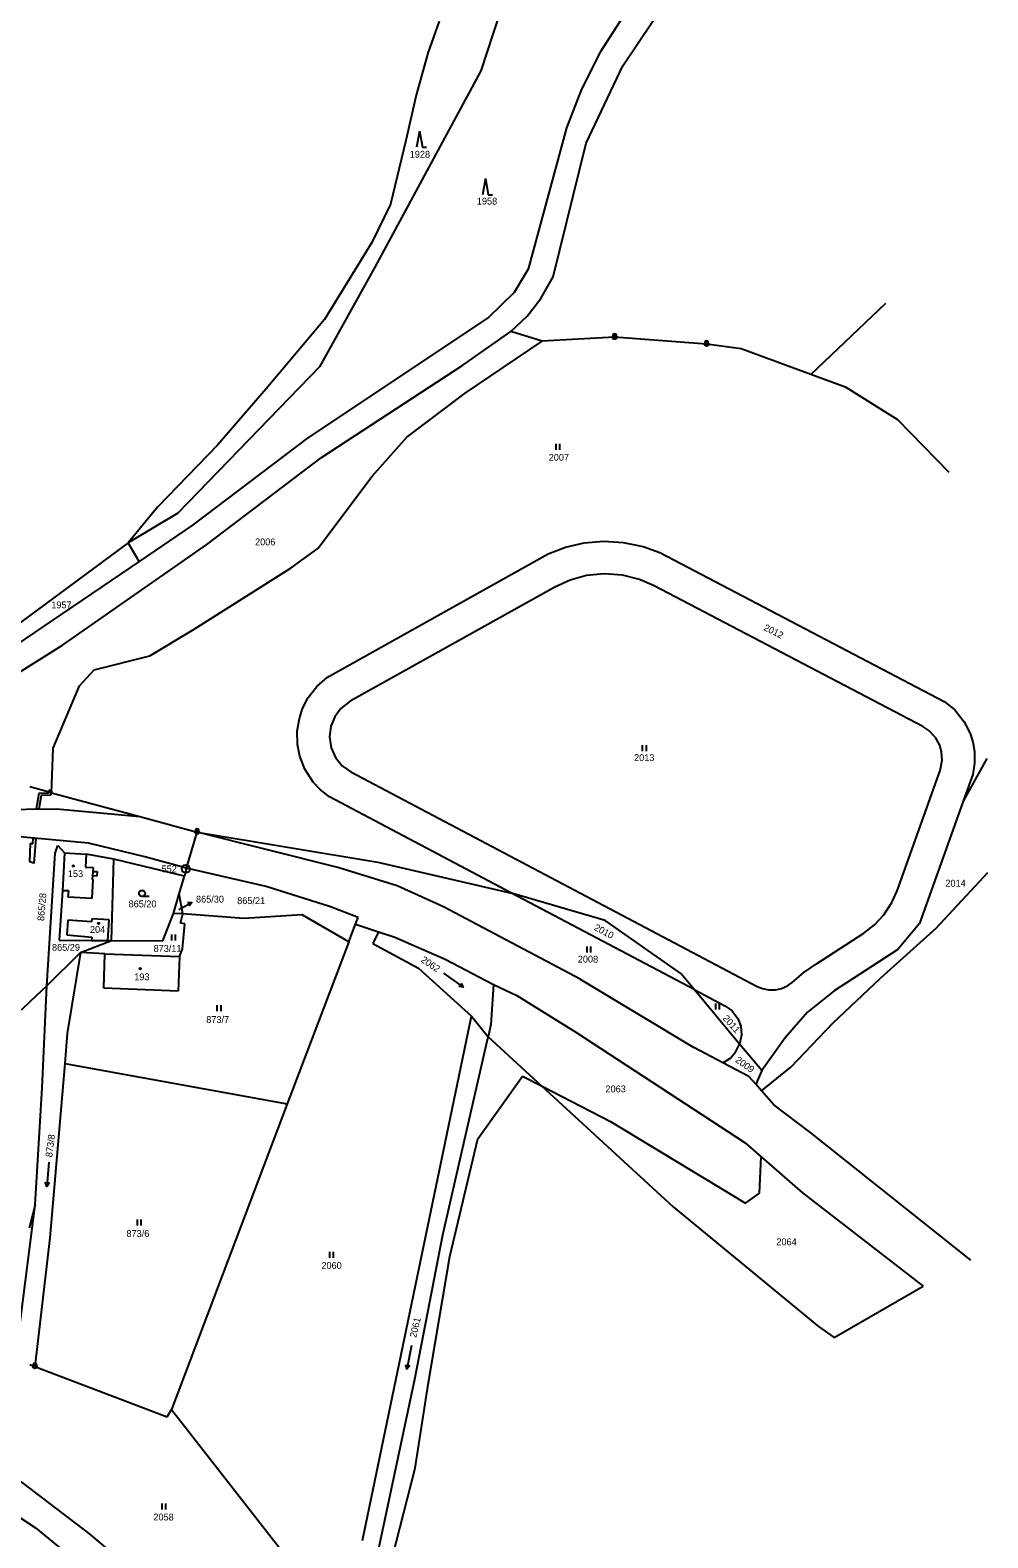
# Model space of a CAD drawing. Extents: x -801826 to -800592, y -1032871 to -1031813.
# Drawn here: x -800830.2 to -800592, y -1032553.2 to -1032178.1 of the extents above; entities that cross this region are included whole.
import ezdxf

# ---------------------------------------------------------------- set-up
doc = ezdxf.new("R2010")
doc.units = 0
for name, color, linetype in [('Vrstva 1', 7, 'Continuous'), ('Vrstva 16', 7, 'Continuous'), ('Vrstva 17', 7, 'Continuous'), ('Vrstva 18', 7, 'Continuous'), ('Vrstva 19', 7, 'Continuous'), ('Vrstva 24', 7, 'Continuous'), ('Vrstva 25', 7, 'Continuous'), ('Vrstva 27', 7, 'Continuous'), ('Vrstva 4', 7, 'Continuous')]:
    doc.layers.add(name, color=color, linetype=linetype)

msp = doc.modelspace()

# ---------------------------------------------------------------- linework, layer by layer
at = {"layer": 'Vrstva 1'}
for p, q in [((-800682.78, -1032186.99), (-800671.93, -1032170.88)), ((-800728.49, -1032175.86), (-800731.3, -1032183.84)), ((-800713.36, -1032173.84), (-800718.08, -1032188.22)), ((-800682.84, -1032174.99), (-800688.39, -1032183.65)), ((-800731.3, -1032183.84), (-800734.21, -1032194.34)), ((-800688.39, -1032183.65), (-800693.07, -1032192.84)), ((-800718.08, -1032188.22), (-800744.46, -1032237.13)), ((-800691.87, -1032206.27), (-800682.78, -1032186.99)), ((-800734.21, -1032194.34), (-800736.73, -1032205.61)), ((-800693.07, -1032192.84), (-800696.78, -1032202.43)), ((-800696.78, -1032202.43), (-800706.37, -1032237.6)), ((-800736.73, -1032205.61), (-800740.62, -1032221.39)), ((-800700.11, -1032239.53), (-800691.87, -1032206.27)), ((-800740.62, -1032221.39), (-800745.26, -1032230.98)), ((-800745.26, -1032230.98), (-800757.04, -1032250.08)), ((-800744.46, -1032237.13), (-800758.24, -1032261.86)), ((-800706.37, -1032237.6), (-800709.85, -1032243.37)), ((-800703.21, -1032244.91), (-800700.11, -1032239.53)), ((-800709.85, -1032243.37), (-800716.24, -1032249.58)), ((-800706.55, -1032249.28), (-800703.21, -1032244.91)), ((-800636.04, -1032263.77), (-800617.35, -1032246.01)), ((-800757.04, -1032250.08), (-800771.52, -1032267.36)), ((-800716.24, -1032249.58), (-800761.19, -1032279.54)), ((-800710.64, -1032253.06), (-800706.55, -1032249.28)), ((-800722.55, -1032261.46), (-800710.64, -1032253.06)), ((-800722.03, -1032268.4), (-800702.87, -1032255.46)), ((-800702.87, -1032255.46), (-800710.64, -1032253.06)), ((-800684.82, -1032254.53), (-800702.87, -1032255.46)), ((-800661.95, -1032256.24), (-800684.82, -1032254.53)), ((-800653.31, -1032257.4), (-800661.95, -1032256.24)), ((-800636.04, -1032263.77), (-800653.31, -1032257.4)), ((-800758.24, -1032261.86), (-800793.49, -1032298.3)), ((-800757.71, -1032284.44), (-800722.55, -1032261.46)), ((-800771.52, -1032267.36), (-800783.65, -1032281.33)), ((-800627.22, -1032267.02), (-800636.04, -1032263.77)), ((-800614.36, -1032275.09), (-800627.22, -1032267.02)), ((-800736.55, -1032279.38), (-800722.03, -1032268.4)), ((-800601.58, -1032288.14), (-800614.36, -1032275.09)), ((-800783.65, -1032281.33), (-800798.54, -1032296.8)), ((-800761.19, -1032279.54), (-800789.82, -1032301.24)), ((-800745.14, -1032289.1), (-800736.55, -1032279.38)), ((-800786.3, -1032306.09), (-800757.71, -1032284.44)), ((-800758.64, -1032307.04), (-800745.14, -1032289.1)), ((-800798.54, -1032296.8), (-800805.86, -1032305.7)), ((-800793.49, -1032298.3), (-800805.86, -1032305.7)), ((-800789.82, -1032301.24), (-800803.13, -1032310.28)), ((-800805.86, -1032305.7), (-800845.05, -1032334.64)), ((-800822.19, -1032331.13), (-800786.3, -1032306.09)), ((-800803.13, -1032310.28), (-800805.86, -1032305.7)), ((-800765.26, -1032311.88), (-800758.64, -1032307.04)), ((-800756.28, -1032339.08), (-800701.36, -1032308.4)), ((-800701.36, -1032308.4), (-800697.01, -1032306.74)), ((-800697.01, -1032306.74), (-800692.42, -1032305.68)), ((-800692.42, -1032305.68), (-800687.52, -1032305.26)), ((-800687.52, -1032305.26), (-800682.72, -1032305.54)), ((-800682.72, -1032305.54), (-800677.74, -1032306.56)), ((-800677.74, -1032306.56), (-800673.59, -1032308.03)), ((-800673.59, -1032308.03), (-800602.82, -1032345.1)), ((-800803.13, -1032310.28), (-800844.97, -1032338.69)), ((-800789.46, -1032327.11), (-800765.26, -1032311.88)), ((-800695.91, -1032314.92), (-800699.74, -1032316.66)), ((-800691.84, -1032313.81), (-800695.91, -1032314.92)), ((-800687.41, -1032313.36), (-800691.84, -1032313.81)), ((-800682.83, -1032313.71), (-800687.41, -1032313.36)), ((-800678.66, -1032314.75), (-800682.83, -1032313.71)), ((-800674.99, -1032316.33), (-800678.66, -1032314.75)), ((-800699.74, -1032316.66), (-800750.63, -1032345.09)), ((-800608.17, -1032351.33), (-800674.99, -1032316.33)), ((-800800.43, -1032333.76), (-800789.46, -1032327.11)), ((-800840.56, -1032342.6), (-800822.19, -1032331.13)), ((-800814.31, -1032337.29), (-800800.43, -1032333.76)), ((-800817.98, -1032341.21), (-800814.31, -1032337.29)), ((-800824.47, -1032356.73), (-800817.98, -1032341.21)), ((-800761.05, -1032344.14), (-800758.9, -1032341.4)), ((-800758.9, -1032341.4), (-800756.28, -1032339.08)), ((-800762.47, -1032346.87), (-800761.05, -1032344.14)), ((-800750.63, -1032345.09), (-800752.91, -1032346.84)), ((-800602.82, -1032345.1), (-800600.23, -1032347.23)), ((-800763.81, -1032352.54), (-800763.26, -1032349.37)), ((-800763.26, -1032349.37), (-800762.47, -1032346.87)), ((-800754.47, -1032348.91), (-800755.43, -1032351.27)), ((-800752.91, -1032346.84), (-800754.47, -1032348.91)), ((-800600.23, -1032347.23), (-800597.89, -1032350.16)), ((-800763.7, -1032355.81), (-800763.81, -1032352.54)), ((-800755.43, -1032351.27), (-800755.75, -1032353.94)), ((-800606.64, -1032352.35), (-800608.17, -1032351.33)), ((-800605.01, -1032354.08), (-800606.64, -1032352.35)), ((-800597.89, -1032350.16), (-800596.41, -1032353.08)), ((-800596.41, -1032353.08), (-800595.75, -1032355.16)), ((-800824.9, -1032367.82), (-800824.47, -1032356.73)), ((-800763.18, -1032358.72), (-800763.7, -1032355.81)), ((-800755.75, -1032353.94), (-800755.35, -1032356.62)), ((-800755.35, -1032356.62), (-800754.24, -1032359.09)), ((-800603.96, -1032356.03), (-800605.01, -1032354.08)), ((-800603.48, -1032357.7), (-800603.96, -1032356.03)), ((-800595.75, -1032355.16), (-800595.32, -1032357.61)), ((-800761.91, -1032361.98), (-800763.18, -1032358.72)), ((-800754.24, -1032359.09), (-800752.59, -1032361.1)), ((-800752.59, -1032361.1), (-800750.42, -1032362.66)), ((-800603.87, -1032362.33), (-800603.35, -1032359.76)), ((-800603.35, -1032359.76), (-800603.48, -1032357.7)), ((-800592.26, -1032359.28), (-800598.08, -1032369.91)), ((-800595.27, -1032360.51), (-800595.72, -1032363.31)), ((-800595.32, -1032357.61), (-800595.27, -1032360.51)), ((-800759.83, -1032365.19), (-800761.91, -1032361.98)), ((-800750.42, -1032362.66), (-800649.35, -1032416.02)), ((-800614.56, -1032392.24), (-800603.87, -1032362.33)), ((-800595.72, -1032363.31), (-800598.08, -1032369.91)), ((-800824.9, -1032367.82), (-800830.33, -1032366.35)), ((-800824.9, -1032367.82), (-800802.98, -1032373.76)), ((-800757.96, -1032367.13), (-800759.83, -1032365.19)), ((-800755.79, -1032368.87), (-800757.96, -1032367.13)), ((-800917.05, -1032372.74), (-800823.7, -1032371.87)), ((-800823.7, -1032371.87), (-800802.98, -1032373.76)), ((-800710.51, -1032392.78), (-800755.79, -1032368.87)), ((-800598.08, -1032369.91), (-800608.97, -1032400.37)), ((-800802.98, -1032373.76), (-800788.68, -1032377.63)), ((-800815.7, -1032380.41), (-800834.63, -1032378.64)), ((-800791.31, -1032386.55), (-800788.68, -1032377.63)), ((-800788.68, -1032377.63), (-800743.76, -1032385.06)), ((-800753.71, -1032386.46), (-800788.68, -1032377.63)), ((-800826.07, -1032415.87), (-800823.97, -1032382.88)), ((-800823.97, -1032382.88), (-800823.34, -1032380.99)), ((-800823.34, -1032380.99), (-800821.71, -1032382.81)), ((-800821.71, -1032382.81), (-800822.15, -1032392.19)), ((-800821.71, -1032382.81), (-800816.27, -1032383.09)), ((-800809.41, -1032384.37), (-800816.27, -1032383.09)), ((-800801.66, -1032383.77), (-800815.7, -1032380.41)), ((-800810.01, -1032404.59), (-800809.41, -1032384.37)), ((-800799.77, -1032386.67), (-800809.41, -1032384.37)), ((-800791.31, -1032386.55), (-800801.66, -1032383.77)), ((-800791.85, -1032388.58), (-800799.77, -1032386.67)), ((-800791.31, -1032386.55), (-800791.85, -1032388.58)), ((-800771.52, -1032391.12), (-800791.31, -1032386.55)), ((-800738.93, -1032390.99), (-800753.71, -1032386.46)), ((-800743.76, -1032385.06), (-800710.51, -1032392.78)), ((-800793.15, -1032393.01), (-800791.85, -1032388.58)), ((-800755.49, -1032396.22), (-800771.52, -1032391.12)), ((-800727.44, -1032396.22), (-800738.93, -1032390.99)), ((-800604.86, -1032401.49), (-800591.98, -1032387.67)), ((-800822.15, -1032392.19), (-800823.01, -1032404.49)), ((-800794.53, -1032397.87), (-800793.15, -1032393.01)), ((-800792.28, -1032397.94), (-800793.15, -1032393.01)), ((-800665.06, -1032416.78), (-800710.51, -1032392.78)), ((-800687.17, -1032399.62), (-800710.51, -1032392.78)), ((-800615.84, -1032395.12), (-800614.56, -1032392.24)), ((-800797.21, -1032404.68), (-800794.53, -1032397.87)), ((-800792.28, -1032397.94), (-800794.53, -1032397.87)), ((-800792.85, -1032400.26), (-800792.28, -1032397.94)), ((-800777.09, -1032399.08), (-800792.28, -1032397.94)), ((-800762.58, -1032398.21), (-800777.09, -1032399.08)), ((-800750.98, -1032404.94), (-800762.58, -1032398.21)), ((-800748.65, -1032398.85), (-800755.49, -1032396.22)), ((-800693.44, -1032414.19), (-800727.44, -1032396.22)), ((-800620.17, -1032400.66), (-800617.85, -1032398.18)), ((-800617.85, -1032398.18), (-800615.84, -1032395.12)), ((-800820.86, -1032399.5), (-800821.13, -1032403.21)), ((-800814.93, -1032399.9), (-800820.86, -1032399.5)), ((-800814.88, -1032399.21), (-800814.93, -1032399.9)), ((-800810.6, -1032399.42), (-800814.88, -1032399.21)), ((-800810.87, -1032404.58), (-800810.6, -1032399.42)), ((-800791.75, -1032400.44), (-800792.85, -1032400.26)), ((-800792.37, -1032406.67), (-800791.75, -1032400.44)), ((-800750.98, -1032404.94), (-800749.3, -1032400.54)), ((-800749.3, -1032400.54), (-800748.65, -1032398.85)), ((-800749.3, -1032400.54), (-800743.61, -1032402.4)), ((-800743.61, -1032402.4), (-800744.94, -1032405.34)), ((-800743.61, -1032402.4), (-800739.52, -1032403.73)), ((-800668.36, -1032412.82), (-800687.17, -1032399.62)), ((-800622.85, -1032402.76), (-800620.17, -1032400.66)), ((-800604.86, -1032401.49), (-800618.74, -1032414.04)), ((-800608.97, -1032400.37), (-800614.41, -1032406.8)), ((-800823.01, -1032404.49), (-800814.97, -1032404.55)), ((-800821.13, -1032403.21), (-800814.9, -1032403.79)), ((-800817.69, -1032407.6), (-800810.01, -1032404.59)), ((-800814.9, -1032403.79), (-800814.97, -1032404.55)), ((-800814.97, -1032404.55), (-800810.87, -1032404.58)), ((-800810.87, -1032404.58), (-800810.01, -1032404.59)), ((-800810.01, -1032404.59), (-800797.21, -1032404.68)), ((-800750.98, -1032404.94), (-800766.25, -1032445.24)), ((-800744.94, -1032405.34), (-800733.61, -1032411.45)), ((-800739.52, -1032403.73), (-800727.02, -1032409.23)), ((-800634.58, -1032410.41), (-800622.85, -1032402.76)), ((-800826.07, -1032415.87), (-800817.69, -1032407.6)), ((-800817.69, -1032407.6), (-800821.05, -1032427.73)), ((-800811.64, -1032407.88), (-800817.69, -1032407.6)), ((-800811.92, -1032416.47), (-800811.64, -1032407.88)), ((-800811.64, -1032407.88), (-800793.07, -1032408.6)), ((-800793.07, -1032408.6), (-800793.39, -1032417.17)), ((-800793.07, -1032408.6), (-800792.37, -1032406.67)), ((-800727.02, -1032409.23), (-800714.92, -1032415.56)), ((-800614.41, -1032406.8), (-800630.21, -1032417.11)), ((-800733.61, -1032411.45), (-800720.4, -1032423.37)), ((-800665.06, -1032416.78), (-800668.36, -1032412.82)), ((-800640.63, -1032415), (-800637.74, -1032412.52)), ((-800637.74, -1032412.52), (-800634.58, -1032410.41)), ((-800830.13, -1032419.65), (-800826.07, -1032415.87)), ((-800827.21, -1032441.23), (-800826.07, -1032415.87)), ((-800793.39, -1032417.17), (-800811.92, -1032416.47)), ((-800714.92, -1032415.56), (-800715.59, -1032425.48)), ((-800714.92, -1032415.56), (-800709.17, -1032418.29)), ((-800693.44, -1032414.19), (-800665.13, -1032431.22)), ((-800653.73, -1032430.33), (-800665.06, -1032416.78)), ((-800665.06, -1032416.78), (-800657.38, -1032420.83)), ((-800649.35, -1032416.02), (-800648.07, -1032416.56)), ((-800648.07, -1032416.56), (-800646.44, -1032416.89)), ((-800646.44, -1032416.89), (-800644.83, -1032416.87)), ((-800644.83, -1032416.87), (-800643.31, -1032416.53)), ((-800643.31, -1032416.53), (-800641.82, -1032415.86)), ((-800641.82, -1032415.86), (-800640.63, -1032415)), ((-800630.21, -1032417.11), (-800636.86, -1032422.4)), ((-800630.44, -1032425.08), (-800618.74, -1032414.04)), ((-800832.38, -1032421.83), (-800830.13, -1032419.65)), ((-800709.17, -1032418.29), (-800694.46, -1032427.37)), ((-800657.38, -1032420.83), (-800655.7, -1032422.02)), ((-800747.51, -1032553.85), (-800720.4, -1032423.37)), ((-800720.4, -1032423.37), (-800716.3, -1032428.56)), ((-800655.7, -1032422.02), (-800654.18, -1032424.01)), ((-800654.18, -1032424.01), (-800653.46, -1032425.9)), ((-800636.86, -1032422.4), (-800642.43, -1032428.81)), ((-800821.05, -1032427.73), (-800821.58, -1032435.17)), ((-800727.57, -1032477.82), (-800716.3, -1032428.56)), ((-800715.59, -1032425.48), (-800716.3, -1032428.56)), ((-800716.3, -1032428.56), (-800703.01, -1032440.76)), ((-800694.46, -1032427.37), (-800652.38, -1032454.93)), ((-800653.26, -1032428.11), (-800653.73, -1032430.33)), ((-800653.46, -1032425.9), (-800653.26, -1032428.11)), ((-800640.97, -1032436.11), (-800630.44, -1032425.08)), ((-800657.91, -1032435.02), (-800665.13, -1032431.22)), ((-800656.04, -1032433.84), (-800654.71, -1032432.2)), ((-800654.71, -1032432.2), (-800653.73, -1032430.33)), ((-800648.24, -1032436.91), (-800653.73, -1032430.33)), ((-800642.43, -1032428.81), (-800648.24, -1032436.91)), ((-800821.58, -1032435.17), (-800825.32, -1032478.51)), ((-800821.58, -1032435.17), (-800766.25, -1032445.24)), ((-800657.91, -1032435.02), (-800656.04, -1032433.84)), ((-800651.42, -1032438.43), (-800657.91, -1032435.02)), ((-800648.29, -1032441.97), (-800640.97, -1032436.11)), ((-800718.84, -1032453.91), (-800707.74, -1032438.32)), ((-800707.74, -1032438.32), (-800703.01, -1032440.76)), ((-800649.74, -1032440.33), (-800651.42, -1032438.43)), ((-800648.24, -1032436.91), (-800649.74, -1032440.33)), ((-800828.95, -1032470.31), (-800827.21, -1032441.23)), ((-800703.01, -1032440.76), (-800670.24, -1032470.85)), ((-800703.01, -1032440.76), (-800685.83, -1032449.61)), ((-800648.29, -1032441.97), (-800649.74, -1032440.33)), ((-800645.22, -1032445.45), (-800648.29, -1032441.97)), ((-800766.25, -1032445.24), (-800795.04, -1032521.25)), ((-800636.05, -1032452.45), (-800645.22, -1032445.45)), ((-800685.83, -1032449.61), (-800652.31, -1032469.95)), ((-800725.86, -1032483.19), (-800718.84, -1032453.91)), ((-800652.38, -1032454.93), (-800648.35, -1032458.43)), ((-800596.18, -1032484.07), (-800636.05, -1032452.45)), ((-800648.79, -1032467.47), (-800648.35, -1032458.43)), ((-800648.35, -1032458.43), (-800638.11, -1032467.31)), ((-800652.31, -1032469.95), (-800648.79, -1032467.47)), ((-800638.11, -1032467.31), (-800608.05, -1032490.56)), ((-800833.85, -1032508.78), (-800828.95, -1032470.31)), ((-800828.95, -1032470.31), (-800830.46, -1032476.14)), ((-800670.24, -1032470.85), (-800634.08, -1032500.56)), ((-800825.32, -1032478.51), (-800829.05, -1032510.51)), ((-800734.56, -1032513.71), (-800727.57, -1032477.82)), ((-800731.18, -1032515.02), (-800725.86, -1032483.19)), ((-800630.23, -1032503.36), (-800608.05, -1032490.56)), ((-800634.08, -1032500.56), (-800630.23, -1032503.36)), ((-800830.33, -1032510.05), (-800829.05, -1032510.51)), ((-800829.05, -1032510.51), (-800796.14, -1032523.03)), ((-800743.69, -1032556.55), (-800734.56, -1032513.71)), ((-800734.46, -1032535.8), (-800731.18, -1032515.02)), ((-800796.14, -1032523.03), (-800795.04, -1032521.25)), ((-800795.04, -1032521.25), (-800753.78, -1032574.05)), ((-800839.16, -1032534.17), (-800815.65, -1032552.08)), ((-800740.12, -1032557.88), (-800734.46, -1032535.8)), ((-800840.22, -1032543.23), (-800828.93, -1032550.72)), ((-800828.93, -1032550.72), (-800808.91, -1032567.02)), ((-800815.65, -1032552.08), (-800776.4, -1032584.81))]:
    msp.add_line(p, q, dxfattribs=at)
at = {"layer": 'Vrstva 16'}
for p, q in [((-800793.27, -1032396.88), (-800792.63, -1032396.54)), ((-800792.63, -1032396.54), (-800789.97, -1032395.15))]:
    msp.add_line(p, q, dxfattribs=at)
msp.add_lwpolyline([(-800791.09, -1032395.17), (-800789.97, -1032395.15), (-800790.63, -1032396.05)], dxfattribs=at)
at = {"layer": 'Vrstva 24'}
for centre, radius in [((-800684.82, -1032254.53), 0.5), ((-800684.82, -1032254.53), 0.0364), ((-800661.95, -1032256.24), 0.5), ((-800661.95, -1032256.24), 0.0364), ((-800788.68, -1032377.63), 0.5), ((-800788.68, -1032377.63), 0.0364), ((-800791.5, -1032386.77), 1), ((-800791.5, -1032386.77), 0.0439), ((-800829.05, -1032510.51), 0.5), ((-800829.05, -1032510.51), 0.0364)]:
    msp.add_circle(centre, radius, dxfattribs=at)
for centre in [(-800684.82, -1032254.16), (-800661.95, -1032255.87), (-800788.68, -1032377.26), (-800829.05, -1032510.14)]:
    msp.add_arc(centre, 0.45, 344.4473, 196.3778, dxfattribs=at)
at = {"layer": 'Vrstva 25'}
for p, q in [((-800733.37, -1032203.25), (-800734.1, -1032207.25)), ((-800733.37, -1032203.25), (-800732.64, -1032207.25)), ((-800732.64, -1032207.25), (-800731.64, -1032207.25)), ((-800716.98, -1032215.07), (-800717.71, -1032219.07)), ((-800716.98, -1032215.07), (-800716.25, -1032219.07)), ((-800716.25, -1032219.07), (-800715.25, -1032219.07)), ((-800699.48, -1032281.06), (-800699.48, -1032282.56)), ((-800698.46, -1032282.56), (-800698.46, -1032281.06)), ((-800677.94, -1032355.96), (-800677.94, -1032357.46)), ((-800676.92, -1032357.46), (-800676.92, -1032355.96)), ((-800800.65, -1032393.61), (-800802.4, -1032393.61)), ((-800795.07, -1032403.09), (-800795.07, -1032404.59)), ((-800794.05, -1032404.59), (-800794.05, -1032403.09)), ((-800691.77, -1032406.07), (-800691.77, -1032407.57)), ((-800690.74, -1032407.57), (-800690.74, -1032406.07)), ((-800727.37, -1032412.7), (-800722.47, -1032416.16)), ((-800783.75, -1032420.65), (-800783.75, -1032422.15)), ((-800782.72, -1032422.15), (-800782.72, -1032420.65)), ((-800659.76, -1032420.24), (-800659.76, -1032421.74)), ((-800658.73, -1032421.74), (-800658.73, -1032420.24)), ((-800825.62, -1032459.76), (-800826.08, -1032465.74)), ((-800803.61, -1032473.95), (-800803.61, -1032475.45)), ((-800802.58, -1032475.45), (-800802.58, -1032473.95)), ((-800755.76, -1032482.01), (-800755.76, -1032483.51)), ((-800754.73, -1032483.51), (-800754.73, -1032482.01)), ((-800735.34, -1032505.3), (-800736.48, -1032511.2)), ((-800797.51, -1032544.66), (-800797.51, -1032546.16)), ((-800796.48, -1032546.16), (-800796.48, -1032544.66))]:
    msp.add_line(p, q, dxfattribs=at)
for points in [[(-800723, -1032415.18), (-800722.47, -1032416.16), (-800723.58, -1032415.99)], [(-800825.51, -1032464.78), (-800826.08, -1032465.74), (-800826.5, -1032464.71)], [(-800735.8, -1032510.31), (-800736.48, -1032511.2), (-800736.78, -1032510.12)]]:
    msp.add_lwpolyline(points, dxfattribs=at)
for centre, radius in [((-800819.47, -1032386.04), 0.175), ((-800802.4, -1032392.86), 0.75), ((-800813.21, -1032400.34), 0.175), ((-800802.84, -1032411.58), 0.175)]:
    msp.add_circle(centre, radius, dxfattribs=at)
at = {"layer": 'Vrstva 27'}
for points in [[(-800825.6, -1032367.63), (-800825.44, -1032367.15), (-800824.88, -1032367.34), (-800824.9, -1032367.82), (-800825.23, -1032368.42), (-800827.52, -1032368.49), (-800827.92, -1032370.9), (-800828.04, -1032371.91), (-800828.64, -1032371.92), (-800828.52, -1032370.82), (-800828.02, -1032367.91), (-800825.67, -1032367.84), (-800825.6, -1032367.63)], [(-800829.45, -1032379.12), (-800828.85, -1032379.18), (-800829.34, -1032385.34), (-800830.35, -1032384.99), (-800830.15, -1032380.47), (-800829.55, -1032380.49), (-800829.45, -1032379.12)]]:
    msp.add_lwpolyline(points, dxfattribs=at)
at = {"layer": 'Vrstva 4'}
for p, q in [((-800816.27, -1032383.09), (-800816.46, -1032386.3)), ((-800816.46, -1032386.3), (-800814.59, -1032386.42)), ((-800814.65, -1032387.39), (-800814.72, -1032388.48)), ((-800814.59, -1032386.42), (-800814.65, -1032387.39)), ((-800814.65, -1032387.39), (-800813.56, -1032387.43)), ((-800813.56, -1032387.43), (-800813.63, -1032388.61)), ((-800814.62, -1032389.41), (-800814.92, -1032394.12)), ((-800814.72, -1032388.48), (-800814.78, -1032389.4)), ((-800814.78, -1032389.4), (-800814.62, -1032389.41)), ((-800813.63, -1032388.61), (-800814.72, -1032388.48)), ((-800820.62, -1032392.26), (-800822.15, -1032392.19)), ((-800820.75, -1032393.79), (-800820.62, -1032392.26)), ((-800814.92, -1032394.12), (-800820.75, -1032393.79))]:
    msp.add_line(p, q, dxfattribs=at)

# ---------------------------------------------------------------- texts
at = {"layer": 'Vrstva 16'}
msp.add_text('865/30', height=1.7, dxfattribs=at).set_placement((-800788.97, -1032395.15))
at = {"layer": 'Vrstva 17'}
msp.add_text('552', height=1.7, dxfattribs=at).set_placement((-800797.54, -1032387.62))
at = {"layer": 'Vrstva 18'}
for s, height, p in [('1928', 1.7, (-800735.8, -1032209.86)), ('1958', 1.7, (-800719.1, -1032221.51)), ('2007', 1.7, (-800701.23, -1032285.25)), ('2006', 1.7, (-800774.28, -1032306.28)), ('1957', 1.7, (-800824.97, -1032321.95)), ('2013', 1.7, (-800679.99, -1032359.95)), ('2014', 1.7, (-800602.54, -1032391.18)), ('865/20', 1.7, (-800805.75, -1032396.33)), ('865/21', 1.7, (-800778.72, -1032395.53)), ('865/30', 0.1, (-800793.49, -1032396.88)), ('865/29', 1.7, (-800824.79, -1032407.14)), ('873/11', 1.7, (-800799.53, -1032407.4)), ('2008', 1.7, (-800693.99, -1032410.07)), ('873/7', 1.7, (-800786.42, -1032425.1)), ('2063', 1.7, (-800687.1, -1032442.35)), ('873/6', 1.7, (-800806.27, -1032478.33)), ('2064', 1.7, (-800644.59, -1032480.39)), ('2060', 1.7, (-800757.77, -1032486.28)), ('2058', 1.7, (-800799.57, -1032548.85))]:
    msp.add_text(s, height=height, dxfattribs=at).set_placement(p)
for s, rotation, p in [('2012', 333.0031, (-800647.9, -1032327.29)), ('865/28', 85.3735, (-800826.76, -1032399.78)), ('2010', 331.9144, (-800690.09, -1032401.87)), ('2062', 325.5547, (-800733.18, -1032409.73)), ('2011', 311.8037, (-800658.07, -1032424.04)), ('2009', 324.2941, (-800654.95, -1032434.66)), ('873/8', 82.7447, (-800824.75, -1032458.57)), ('2061', 76.5472, (-800734.2, -1032503.49))]:
    msp.add_text(s, height=1.7, rotation=rotation, dxfattribs=at).set_placement(p)
at = {"layer": 'Vrstva 19'}
for s, p in [('153', (-800820.85, -1032388.81)), ('204', (-800815.35, -1032402.68)), ('193', (-800804.34, -1032414.47))]:
    msp.add_text(s, height=1.7, dxfattribs=at).set_placement(p)

doc.saveas('drawing.dxf')
